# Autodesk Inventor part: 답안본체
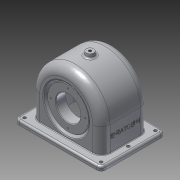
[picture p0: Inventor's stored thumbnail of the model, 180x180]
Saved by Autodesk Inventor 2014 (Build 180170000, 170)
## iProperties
Created: 2015-09
Part Number: 답안본체
Material: 알루미늄 6061
Document SubType Name: Modeling
Designer: basic
Density: 2.71 g/cm^3
Appearance: 알루미늄 - 평지
Mass: 723.087 g
Surface Area: 889.802 cm^2
Volume: 266.822 cm^3
Author: basic
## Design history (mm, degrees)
sketch "스케치2"
  geometry: L1 (57, 47)-(57, 0); L2 (-57, 47)-(-57, 0); L3 (-57, 0)-(57, 0); A1 r 57 centre (0, 47) between (57, 47) and (-57, 47); 2 further points
  constraints: 6 end point, 2 coincident, 2 point on circle, 2 tangent, 1 centre point, 1 midpoint, 1 parallel, 1 perpendicular, 1 vertical
  dimensions: "d1" = 47 distance from line of L3 A1.centre; "d2" = 104 dimension on A1 L3
extrude "돌출1" new body sketch "스케치2" stored distance "d3" = 77; taper "d4" = 0 deg
sketch "스케치3"
  geometry: L1 (114, -77)-(114, 0) reference; L2 (0, 0)-(114, 0) reference; L3 (0, -77)-(0, 0) reference; L4 (114, -77)-(0, -77) reference; L5 (-13, 13.5)-(127, 13.5); L6 (127, 13.5)-(127, -90.5); L7 (127, -90.5)-(-13, -90.5); L8 (-13, -90.5)-(-13, 13.5); 3 further points
  constraints: 8 end point, 2 midpoint, 2 parallel, 1 horizontal, 1 horizontal alignment, 1 perpendicular, 1 vertical alignment
  dimensions: "d6" = 140 distance of L5.start L5.end; "d7" = 104 distance of L5.end L6.end
extrude "돌출2" join sketch "스케치3" distance "d8" = 7; taper "d9" = 0 deg
node "작업 평면1"
sketch "스케치4"
  geometry: C1 r 6 at (-70, -52); 1 further point
  constraints: 1 centre point, 1 coincident
  dimensions: "d11" = 12 diameter of C1
extrude "돌출3" join sketch "스케치4" distance "d12" = 7; taper "d13" = 10 deg
sketch "스케치5"
  geometry: C1 r 31 at (0, -47); A1 r 57 centre (0, -47) between (-57, -47) and (57, -47) reference; 1 further point
  constraints: 1 centre point, 1 coincident
  dimensions: "d14" = 62 diameter of C1
extrude "돌출4" join sketch "스케치5" distance "d15" = 10; taper "d16" = 0 deg
fillet "모깎기1" dims "d17" = 7
sketch "스케치6"
  geometry: L1 (-127, 6.5)-(-127, -83.5) reference; L2 (-120, -90.5)-(6, -90.5) reference; 7 further points
  constraints: 4 vertical alignment, 3 horizontal alignment
  dimensions: "d18" = 8 distance from line of L2 point (-119, -82.5); "d19" = 44 distance of point (-119, -38.5) point (-119, -82.5); "d20" = 44 distance of point (-119, 5.5) point (-119, -38.5); "d21" = 8 distance from line of L1 point (-119, 5.5); "d110" = 124 distance of point (5, 5.5) point (-119, 5.5)
hole "구멍1" sketch "스케치6" at (-119, 5.5), (5, 5.5), (5, -38.5), (5, -82.5), (-119, -82.5), (-119, -38.5) diameter "d23" = 5; stored, may be unused: countersink angle "d27" = 90 deg, drill point angle "d29" = 118 deg; dims "d24" = 6, "d25" = 4, "d26" = 2, "d28" = 8
hole "구멍2" diameter "d32" = 4.459; stored, may be unused: countersink angle "d36" = 90 deg, drill point angle "d38" = 118 deg; dims "d33" = 6, "d34" = 4, "d35" = 2, "d37" = 8, "d39" = 10, "d40" = 10
node "작업 평면2"
sketch "스케치10"
  geometry: L1 (-51, 47)-(-51, 0); L2 (51, 47)-(51, 0); L3 (63, 0)-(-63, 0) reference; L4 (-57, 7)-(-57, 47) reference; A1 r 57 centre (0, 47) between (57, 47) and (-57, 47) reference; A2 r 51 centre (0, 47) between (51, 47) and (-51, 47); 1 further point
  constraints: 4 end point, 2 point on circle, 2 point on line, 2 tangent, 1 centre point, 1 parallel, 1 vertical
  dimensions: "d51" = 51 radius of A2
extrude "돌출6" cut sketch "스케치10" stored distance "d52" = 67; taper "d53" = 0 deg
node "작업 평면3"
sketch "스케치11"
  geometry: C1 r 28 at (0, 47); 1 further point
  constraints: 1 centre point, 1 vertical alignment
  dimensions: "d55" = 56 diameter of C1; "d56" = 47 distance of point (0, 0) C1.centre
extrude "돌출7" join sketch "스케치11" stored distance "d57" = 67; taper "d58" = 40 deg
sketch "스케치13"
  geometry: L1 (-19.5, 75)-(-33.5, 86.747) reference; L2 (-38.5, 104)-(-38.5, 47) reference; L3 (-38.5, 47)-(-38.5, 7) reference; L4 (-38.5, 47)-(-35.5, 47); L5 (-35.5, 47)-(-35.5, 80); L6 (-33.833, 80.5)-(-38.5, 84.416); L7 (-35.5, 80)-(-33.833, 80); L8 (-33.833, 80)-(-33.833, 80.5); 1 further point
  constraints: 10 end point, 3 perpendicular, 1 parallel, 1 point on line
  dimensions: "d64" = 3 distance between parallel lines of L2 L5; "d65" = 5 distance between parallel lines of L1 L6; "d66" = 66 diameter of L7 L4; "d67" = 0.5 distance of L7.end L6.start
revolve "회전1" sketch "스케치13" stored, may be unused: angle "d68" = 90 deg
fillet "모깎기2" dims "d69" = 0.5
fillet "모깎기3" dims "d70" = 0.5
hole "구멍3" diameter "d73" = 40; stored, may be unused: countersink angle "d77" = 90 deg, drill point angle "d79" = 118 deg; dims "d71" = 10, "d72" = 10, "d74" = 6, "d75" = 4, "d76" = 2, "d78" = 8
fillet "모깎기4" dims "d80" = 14
fillet "모깎기5" dims "d81" = 1
fillet "모깎기6" dims "d82" = 9
fillet "모깎기7" dims "d83" = 3
chamfer "모따기1" distance "d85" = 1; stored, may be unused: second distance "d86" = 2, angle "d87" = 45 deg
sketch "스케치14"
  geometry: C1 r 33 at (0, 0) reference; C2 r 21 at (0, 0) reference; A1 r 28 centre (0, 0) between (0, 28) and (28, 0); 3 further points
  constraints: 4 point on circle, 2 horizontal alignment, 2 vertical alignment, 1 centre point, 1 coincident
  dimensions: "d88" = 56 diameter of A1
hole "구멍4" sketch "스케치14" at (0, 28), (28, 0), (-28, 0), (0, -28) diameter "d89" = 2.459; stored, may be unused: countersink angle "d93" = 90 deg, drill point angle "d95" = 118 deg; dims "d90" = 7, "d91" = 4, "d92" = 2, "d94" = 9
sketch "스케치15"
  geometry: C1 r 31 at (0, 0) reference; C2 r 21 at (0, 0) reference; A1 r 24 centre (0, 0) between (0, 24) and (24, 0); 3 further points
  constraints: 4 point on circle, 2 horizontal alignment, 2 vertical alignment, 1 centre point, 1 coincident
  dimensions: "d96" = 48 diameter of A1
hole "구멍5" sketch "스케치15" at (0, 24), (24, 0), (-24, 0), (0, -24) diameter "d97" = 2.459; stored, may be unused: countersink angle "d101" = 90 deg, drill point angle "d103" = 118 deg; dims "d98" = 6, "d99" = 4, "d100" = 2, "d102" = 8
fillet "모깎기9" dims "d104" = 3
fillet "모깎기10" dims "d105" = 3
sketch "스케치16"
  geometry: L1 (0, -14)-(39, -14) reference; L2 (47, -20.5)-(47, 69.5) reference; 2 further points
  constraints: 1 other
  dimensions: "d106" = 38.5 distance from line of L1 point (17, 24.5); "d107" = 30 distance from line of L2 point (17, 24.5)
feature "엠보싱1" sketch "스케치16" dims "d108" = 0.5, "d109" = 0
node "솔리드1"
other parameters: "d46" = -19, "d54" = -19
